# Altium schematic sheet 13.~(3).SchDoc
size 398 x 287 mm
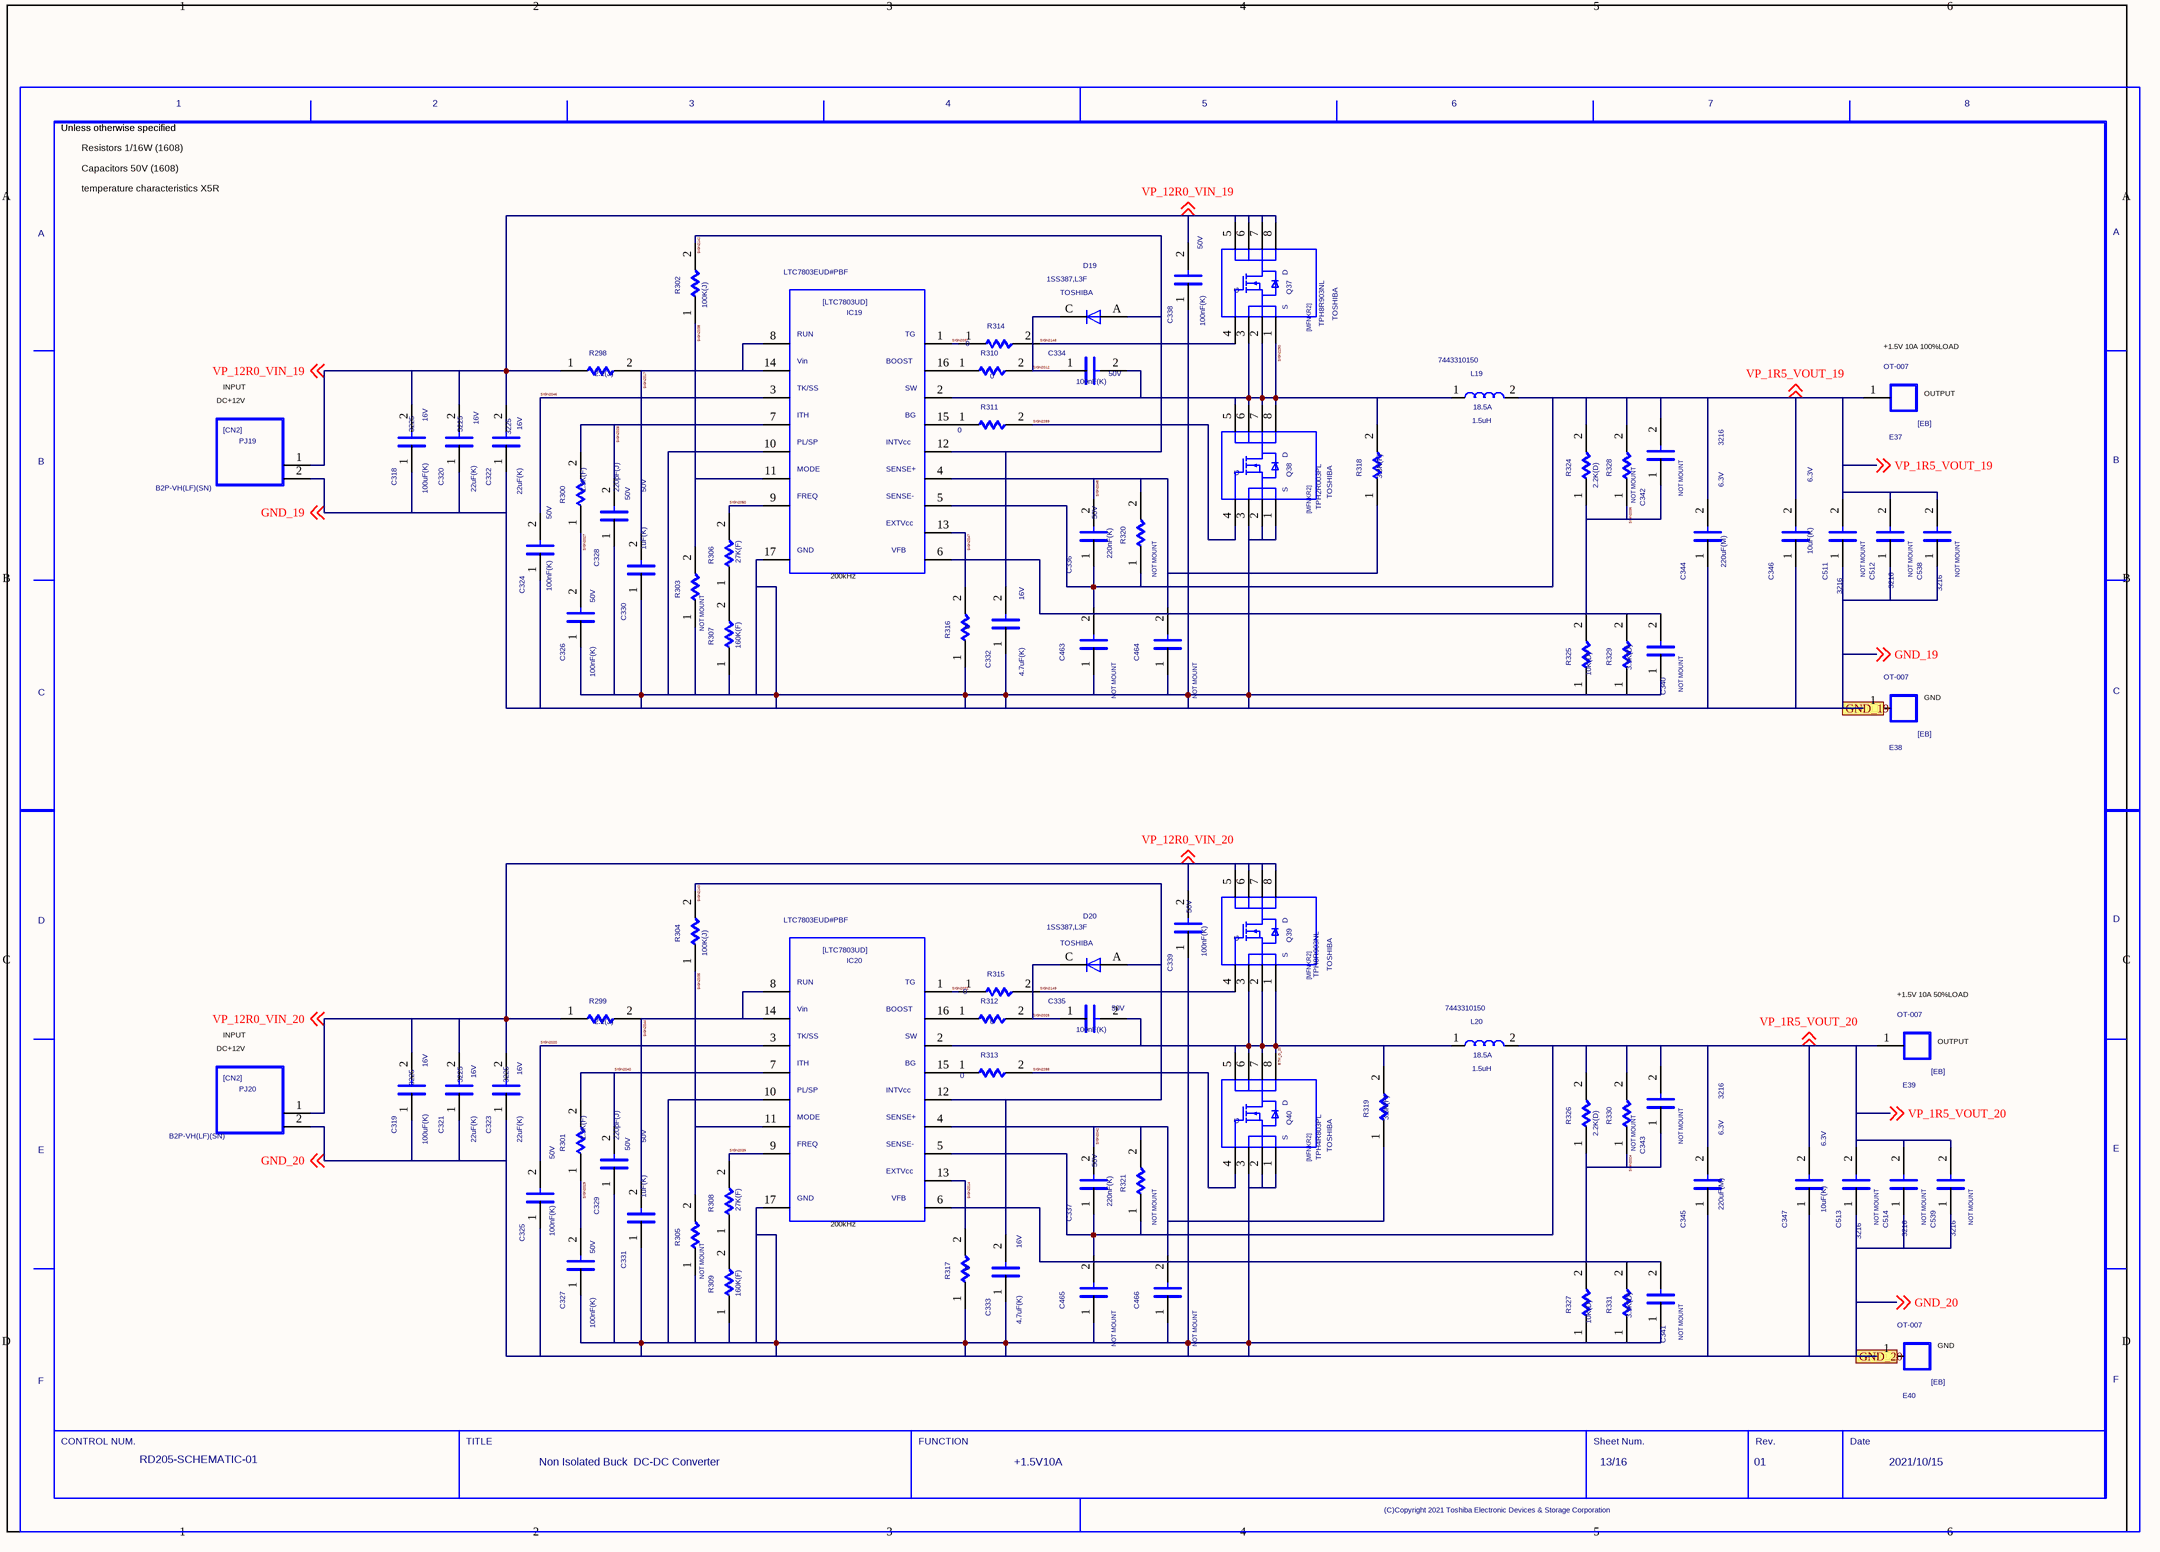
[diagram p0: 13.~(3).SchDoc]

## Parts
C318  SIZECODESMD: 3225  VAL2: 16V  VAL1: 100uF(K)  (hidden comment: C)
C319  SIZECODESMD: 3225  VAL2: 16V  VAL1: 100uF(K)  (hidden comment: C)
C320  SIZECODESMD: 3225  VAL2: 16V  VAL1: 22uF(K)  (hidden comment: C)
C321  SIZECODESMD: 3225  VAL2: 16V  VAL1: 22uF(K)  (hidden comment: C)
C322  SIZECODESMD: 3225  VAL2: 16V  VAL1: 22uF(K)  (hidden comment: C)
C323  SIZECODESMD: 3225  VAL2: 16V  VAL1: 22uF(K)  (hidden comment: C)
C324  VAL2: 50V  VAL1: 100nF(K)  (hidden comment: C)
C325  VAL2: 50V  VAL1: 100nF(K)  (hidden comment: C)
C326  VAL2: 50V  VAL1: 100nF(K)  (hidden comment: C)
C327  VAL2: 50V  VAL1: 100nF(K)  (hidden comment: C)
C328  VAL2: 50V  VAL1: 220pF(J)  (hidden comment: C)
C329  VAL2: 50V  VAL1: 220pF(J)  (hidden comment: C)
C330  VAL2: 50V  VAL1: 1uF(K)  (hidden comment: C)
C331  VAL2: 50V  VAL1: 1uF(K)  (hidden comment: C)
C332  VAL2: 16V  VAL1: 4.7uF(K)  (hidden comment: C)
C333  VAL2: 16V  VAL1: 4.7uF(K)  (hidden comment: C)
C334  VAL2: 50V  VAL1: 100nF(K)  (hidden comment: C)
C335  VAL2: 50V  VAL1: 100nF(K)  (hidden comment: C)
C336  VAL2: 50V  VAL1: 220nF(K)  (hidden comment: C)
C337  VAL2: 50V  VAL1: 220nF(K)  (hidden comment: C)
C338  VAL2: 50V  VAL1: 100nF(K)  (hidden comment: C)
C339  VAL2: 50V  VAL1: 100nF(K)  (hidden comment: C)
C340  NOTMOUNT: NOT MOUNT  (hidden comment: C)
C341  NOTMOUNT: NOT MOUNT  (hidden comment: C)
C342  NOTMOUNT: NOT MOUNT  (hidden comment: C)
C343  NOTMOUNT: NOT MOUNT  (hidden comment: C)
C344  SIZECODESMD: 3216  VAL2: 6.3V  VAL1: 220uF(M)  (hidden comment: C)
C345  SIZECODESMD: 3216  VAL2: 6.3V  VAL1: 220uF(M)  (hidden comment: C)
C346  VAL2: 6.3V  VAL1: 10uF(K)  (hidden comment: C)
C347  VAL2: 6.3V  VAL1: 10uF(K)  (hidden comment: C)
C463  NOTMOUNT: NOT MOUNT  (hidden comment: C)
C464  NOTMOUNT: NOT MOUNT  (hidden comment: C)
C465  NOTMOUNT: NOT MOUNT  (hidden comment: C)
C466  NOTMOUNT: NOT MOUNT  (hidden comment: C)
C511  NOTMOUNT: NOT MOUNT  SIZECODESMD: 3216  (hidden comment: C)
C512  NOTMOUNT: NOT MOUNT  SIZECODESMD: 3216  (hidden comment: C)
C513  NOTMOUNT: NOT MOUNT  SIZECODESMD: 3216  (hidden comment: C)
C514  NOTMOUNT: NOT MOUNT  SIZECODESMD: 3216  (hidden comment: C)
C538  NOTMOUNT: NOT MOUNT  SIZECODESMD: 3216  (hidden comment: C)
C539  NOTMOUNT: NOT MOUNT  SIZECODESMD: 3216  (hidden comment: C)
D19  USERCOMPTEXT3: TOSHIBA  VAL3: 1SS387,L3F  (hidden comment: D)
D20  USERCOMPTEXT3: TOSHIBA  VAL3: 1SS387,L3F  (hidden comment: D)
E37  VAL3: OT-007  (hidden comment: EB)
E38  VAL3: OT-007  (hidden comment: EB)
E39  VAL3: OT-007  (hidden comment: EB)
E40  VAL3: OT-007  (hidden comment: EB)
IC19  VAL3: LTC7803EUD#PBF  (hidden comment: LTC7803UD)
IC20  VAL3: LTC7803EUD#PBF  (hidden comment: LTC7803UD)
L19  VAL3: 7443310150  VAL2: 18.5A  VAL1: 1.5uH  (hidden comment: L)
L20  VAL3: 7443310150  VAL2: 18.5A  VAL1: 1.5uH  (hidden comment: L)
PJ19  VAL3: B2P-VH(LF)(SN)  (hidden comment: CN2)
PJ20  VAL3: B2P-VH(LF)(SN)  (hidden comment: CN2)
Q37  USERCOMPTEXT3: TOSHIBA  VAL3: TPH8R903NL  (hidden comment: MFNKR2)
Q38  USERCOMPTEXT3: TOSHIBA  VAL3: TPH2R003PL  (hidden comment: MFNKR2)
Q39  USERCOMPTEXT3: TOSHIBA  VAL3: TPH8R903NL  (hidden comment: MFNKR2)
Q40  USERCOMPTEXT3: TOSHIBA  VAL3: TPH4R803PL  (hidden comment: MFNKR2)
R298  VAL1: 2.2(J)  (hidden comment: R)
R299  VAL1: 2.2(J)  (hidden comment: R)
R300  VAL1: 1.3K(F)  (hidden comment: R)
R301  VAL1: 1.3K(F)  (hidden comment: R)
R302  VAL1: 100K(J)  (hidden comment: R)
R303  NOTMOUNT: NOT MOUNT  (hidden comment: R)
R304  VAL1: 100K(J)  (hidden comment: R)
R305  NOTMOUNT: NOT MOUNT  (hidden comment: R)
R306  VAL1: 27K(F)  (hidden comment: R)
R307  VAL1: 160K(F)  (hidden comment: R)
R308  VAL1: 27K(F)  (hidden comment: R)
R309  VAL1: 160K(F)  (hidden comment: R)
R310  VAL1: 0  (hidden comment: R)
R311  VAL1: 0  (hidden comment: R)
R312  VAL1: 0  (hidden comment: R)
R313  VAL1: 0  (hidden comment: R)
R314  VAL1: 0  (hidden comment: R)
R315  VAL1: 0  (hidden comment: R)
R316  VAL1: 0  (hidden comment: R)
R317  VAL1: 0  (hidden comment: R)
R318  VAL1: 3.3K(F)  (hidden comment: R)
R319  VAL1: 3.3K(F)  (hidden comment: R)
R320  NOTMOUNT: NOT MOUNT  (hidden comment: R)
R321  NOTMOUNT: NOT MOUNT  (hidden comment: R)
R324  VAL1: 2.2K(D)  (hidden comment: R)
R325  VAL1: 10K(D)  (hidden comment: R)
R326  VAL1: 2.2K(D)  (hidden comment: R)
R327  VAL1: 10K(D)  (hidden comment: R)
R328  NOTMOUNT: NOT MOUNT  (hidden comment: R)
R329  VAL1: 3.3K(D)  (hidden comment: R)
R330  NOTMOUNT: NOT MOUNT  (hidden comment: R)
R331  VAL1: 3.3K(D)  (hidden comment: R)
U?  DATE: 2021/10/15  SHEETNUMBER: 13/16  TITLE: Non Isolated Buck / DC-DC Converter  REVISION: 01  DRAWINGNUMBER: RD205-SCHEMATIC-01  FUNCTION: +1.5V10A  (hidden comment: WAKU_DEF100)

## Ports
GND_19, GND_20

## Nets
BTM_D_20: C335.2 IC20.2 L20.1 Q39.1 Q39.2 Q39.3 Q40.5 Q40.6 Q40.7 Q40.8 R319.2
GND_19: C318.1 C320.1 C322.1 C324.1 C326.1 C328.1 C330.1 C332.1 C338.1 C340.1 C344.1 C346.1 C463.1 C464.1 C511.1 C512.1 C538.1 E38.1 IC19.10 IC19.17 PJ19.2 Q38.1 Q38.2 Q38.3 R303.1 R307.1 R316.1 R325.1 R329.1 ; off-sheet GND_19, port GND_19
GND_20: C319.1 C321.1 C323.1 C325.1 C327.1 C329.1 C331.1 C333.1 C339.1 C341.1 C345.1 C347.1 C465.1 C466.1 C513.1 C514.1 C539.1 E40.1 IC20.10 IC20.17 PJ20.2 Q40.1 Q40.2 Q40.3 R305.1 R309.1 R317.1 R327.1 R331.1 ; off-sheet GND_20, port GND_20
SIGN2012: C334.1 D19.C R310.2
SIGN2014: IC20.13 R317.2
SIGN2017: C330.2 IC19.8 IC19.14 R298.2
SIGN2020: C325.2 IC20.3
SIGN2024: C341.2 C343.1 IC20.6 R326.1 R327.2 R330.1 R331.2
SIGN2026: C335.1 D20.C R312.2
SIGN2027: C326.2 R300.1
SIGN2028: C328.2 IC19.7 R300.2
SIGN2029: C327.2 R301.1
SIGN2031: IC20.1 R315.1
SIGN2035: IC20.11 R304.1 R305.2
SIGN2036: C340.2 C342.1 IC19.6 R324.1 R325.2 R328.1 R329.2
SIGN2037: IC19.1 R314.1
SIGN2038: IC19.11 R302.1 R303.2
SIGN2039: IC20.9 R308.2
SIGN2040: C329.2 IC20.7 R301.2
SIGN2042: C337.2 C466.2 IC20.4 R319.1 R321.2
SIGN2044: C331.2 IC20.8 IC20.14 R299.2
SIGN2045: C336.2 C464.2 IC19.4 R318.1 R320.2
SIGN2046: C324.2 IC19.3
SIGN2047: IC19.13 R316.2
SIGN2050: IC19.9 R306.2
SIGN2142: C332.2 D19.A IC19.12 R302.2
SIGN2143: C333.2 D20.A IC20.12 R304.2
SIGN2148: Q37.4 R314.2
SIGN2149: Q39.4 R315.2
SIGN2288: Q40.4 R313.2
SIGN2289: Q38.4 R311.2
SIGN2290: C334.2 IC19.2 L19.1 Q37.1 Q37.2 Q37.3 Q38.5 Q38.6 Q38.7 Q38.8 R318.2
VP_1R5_VOUT_19: C336.1 C342.2 C344.2 C346.2 C463.2 C511.2 C512.2 C538.2 E37.1 IC19.5 L19.2 R320.1 R324.2 R328.2 ; off-sheet VP_1R5_VOUT_19
VP_1R5_VOUT_20: C337.1 C343.2 C345.2 C347.2 C465.2 C513.2 C514.2 C539.2 E39.1 IC20.5 L20.2 R321.1 R326.2 R330.2 ; off-sheet VP_1R5_VOUT_20
VP_12R0_VIN_19: C318.2 C320.2 C322.2 C338.2 PJ19.1 Q37.5 Q37.6 Q37.7 Q37.8 R298.1 ; off-sheet VP_12R0_VIN_19
VP_12R0_VIN_20: C319.2 C321.2 C323.2 C339.2 PJ20.1 Q39.5 Q39.6 Q39.7 Q39.8 R299.1 ; off-sheet VP_12R0_VIN_20
NetIC19_15: IC19.15 R311.1
NetIC19_16: IC19.16 R310.1
NetIC20_15: IC20.15 R313.1
NetIC20_16: IC20.16 R312.1
NetR306_1: R306.1 R307.2
NetR308_1: R308.1 R309.2

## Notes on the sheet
- Unless otherwise specified
- Resistors 1/16W (1608)
- Capacitors 50V (1608)
- temperature characteristics X5R
- DC+12V
- INPUT
- (near E37) +1.5V 10A 100%LOAD
- (near E37) OUTPUT
- (near IC19) 200kHz
- (near E38) GND
- (near E39) +1.5V 10A 50%LOAD
- (near E39) OUTPUT
- (near IC20) 200kHz
- (near E40) GND

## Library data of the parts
C318 C319 = C: SQ_PART_MODEL: CON_100n; FNPARTSNAMEG: CHIP CERAMIC CAPACITOR (3225); USEINPARTSLIST: YES; OriginalSymbolOrigin: (2540,7620); MFSOLDERINGPROP: .; TEMPCHARACTERI2: B; MFFORMINGDIVP: KC; OUMECLASSIFICATION: セラミックコンデンサ; MFMOUNTSYMBOLP: 90; CDMASTERCADCELG: DC903A; PCODE: P03276001115; FNCLASSCODEG: P03-03; MAXGCOUNT: 1; RATEDVOLTAGE: 250; COMPONENTNAME: G36030160049; OUMEMAKER: KYC 京セラ; MFPACKAGEMETHOP: S; NOMINALCAPACITA: 100n; OUMEMAKERKATAMEI: CF32W5R104K250AT; CAPACITANCETOLE: K
C320-C323 = C: SQ_PART_MODEL: CON_22u; FNPARTSNAMEG: CHIP CERAMIC CAPACITOR (3225); USEINPARTSLIST: YES; OriginalSymbolOrigin: (2540,7620); MFSOLDERINGPROP: .; TEMPCHARACTERI2: B; MFFORMINGDIVP: KC; OUMECLASSIFICATION: セラミックコンデンサ; MFMOUNTSYMBOLP: 80; CDMASTERCADCELG: DC903A; PCODE: P03043035626; FNCLASSCODEG: P03-03; MAXGCOUNT: 1; RATEDVOLTAGE: 6.3; COMPONENTNAME: G36030119054; OUMEMAKER: TYD 太陽誘電; MFPACKAGEMETHOP: S; NOMINALCAPACITA: 22u; OUMEMAKERKATAMEI: JMK325BJ226KM-T; CAPACITANCETOLE: K
C324-C327 C334 C335 C338 C339 = C: SQ_PART_MODEL: CON_100n; FNPARTSNAMEG: CHIP CERAMIC CAPACITOR (1608); USEINPARTSLIST: YES; OriginalSymbolOrigin: (2540,7620); MFSOLDERINGPROP: .; TEMPCHARACTERI2: B; MFFORMINGDIVP: KC; OUMECLASSIFICATION: セラミックコンデンサ; SIZECODESMD: 1608; MFMOUNTSYMBOLP: 80; CDMASTERCADCELG: C8100E; PCODE: P03B000000E4; FNCLASSCODEG: P03-03; MAXGCOUNT: 1; RATEDVOLTAGE: 16; COMPONENTNAME: GDM030000598; OUMEMAKER: MRT 村田製作所; MFPACKAGEMETHOP: S; NOMINALCAPACITA: 100n; OUMEMAKERKATAMEI: GRM188B11C104KA01C; CAPACITANCETOLE: K
C328 C329 = C: SQ_PART_MODEL: CON_220p; FNPARTSNAMEG: CHIP CERAMIC CAPACITOR (1608); USEINPARTSLIST: YES; OriginalSymbolOrigin: (2540,7620); CDMASTERCADCELG: C8100E; MFSOLDERINGPROP: .; TEMPCHARACTERI2: CH; MFFORMINGDIVP: KC; OUMECLASSIFICATION: セラミックコンデンサ; SIZECODESMD: 1608; MFMOUNTSYMBOLP: 80; PCODE: P03039269127; FNCLASSCODEG: P03-03; MAXGCOUNT: 1; RATEDVOLTAGE: 50; COMPONENTNAME: GDM030000578; OUMEMAKER: KYC 京セラ; MFPACKAGEMETHOP: S; NOMINALCAPACITA: 220p; OUMEMAKERKATAMEI: CM105CH221J50AT; CAPACITANCETOLE: J
C330 C331 = C: SQ_PART_MODEL: CON_1u; FNPARTSNAMEG: CHIP CERAMIC CAPACITOR (1608); USEINPARTSLIST: YES; OriginalSymbolOrigin: (2540,7620); MFSOLDERINGPROP: .; TEMPCHARACTERI2: B; MFFORMINGDIVP: KC; OUMECLASSIFICATION: セラミックコンデンサ; SIZECODESMD: 1608; MFMOUNTSYMBOLP: 80; CDMASTERCADCELG: C8100E; PCODE: P03039ACE122; FNCLASSCODEG: P03-03; MAXGCOUNT: 1; RATEDVOLTAGE: 6.3; COMPONENTNAME: G36030104159; OUMEMAKER: KYC 京セラ; MFPACKAGEMETHOP: S; NOMINALCAPACITA: 1u; OUMEMAKERKATAMEI: CM105B105K06ATN; CAPACITANCETOLE: K
C332 C333 = C: SQ_PART_MODEL: CON_4.7u; FNPARTSNAMEG: CHIP CERAMIC CAPACITOR (1608); USEINPARTSLIST: YES; OriginalSymbolOrigin: (2540,7620); MFSOLDERINGPROP: .; TEMPCHARACTERI2: B; MFFORMINGDIVP: KC; OUMECLASSIFICATION: セラミックコンデンサ; SIZECODESMD: 1608; MFMOUNTSYMBOLP: 80; CDMASTERCADCELG: C8100E; PCODE: P03B000000MS; FNCLASSCODEG: P03-03; MAXGCOUNT: 1; RATEDVOLTAGE: 4; COMPONENTNAME: GDM030000053; OUMEMAKER: KYC 京セラ; MFPACKAGEMETHOP: S; NOMINALCAPACITA: 4.7u; OUMEMAKERKATAMEI: CM105B475M04AT; CAPACITANCETOLE: M
C336 C337 = C: SQ_PART_MODEL: CON_220n; FNPARTSNAMEG: CHIP CERAMIC CAPACITOR (1608); PARTCOMMENT: 代表セル<KC0008> がフットプリントに登録されていません。; USEINPARTSLIST: YES; OriginalSymbolOrigin: (2540,7620); MFSOLDERINGPROP: .; TEMPCHARACTERI2: B; MFFORMINGDIVP: KC; OUMECLASSIFICATION: セラミックコンデンサ; SIZECODESMD: 1608; MFMOUNTSYMBOLP: 80; CDMASTERCADCELG: KC0008; PCODE: P03B000001L3; FNCLASSCODEG: P03-03; MAXGCOUNT: 1; RATEDVOLTAGE: 16; COMPONENTNAME: GDM030001129; OUMEMAKER: MRT 村田製作所; MFPACKAGEMETHOP: S; NOMINALCAPACITA: 220n; OUMEMAKERKATAMEI: GRM188B11C224KA01D; CAPACITANCETOLE: K
C340-C343 = C: SQ_PART_MODEL: CON_100p; FNPARTSNAMEG: CHIP CERAMIC CAPACITOR (1608); USEINPARTSLIST: YES; OriginalSymbolOrigin: (2540,7620); TOLERANCE: J; ASIMVALUE: 100P; MFSOLDERINGPROP: .; TEMPCHARACTERI2: CH; MFFORMINGDIVP: KC; OUMECLASSIFICATION: セラミックコンデンサ; SIZECODESMD: 1608; MFMOUNTSYMBOLP: 80; CDMASTERCADCELG: C8100E; PCODE: P03039177125; FNCLASSCODEG: P03-03; MAXGCOUNT: 1; RATEDVOLTAGE: 50; COMPONENTNAME: G36030011365; OUMEMAKER: KYC 京セラ; MFPACKAGEMETHOP: S; OUMEMAKERKATAMEI: CM105CH101J50AT; VAL2: 50V; VAL1: 100pF(J)
C344 C345 = C: SQ_PART_MODEL: CON_22u; FNPARTSNAMEG: CHIP CERAMIC CAPACITOR (3216); USEINPARTSLIST: YES; OriginalSymbolOrigin: (2540,7620); MFSOLDERINGPROP: .; TEMPCHARACTERI2: B; MFFORMINGDIVP: KC; OUMECLASSIFICATION: セラミックコンデンサ; MFMOUNTSYMBOLP: 80; CDMASTERCADCELG: DC901A; PCODE: P03B0000004V; FNCLASSCODEG: P03-03; MAXGCOUNT: 1; RATEDVOLTAGE: 6.3; COMPONENTNAME: GDM030000020; OUMEMAKER: KYC 京セラ; MFPACKAGEMETHOP: S; NOMINALCAPACITA: 22u; OUMEMAKERKATAMEI: CM316B226M06AT; CAPACITANCETOLE: M
C346 C347 = C: SQ_PART_MODEL: CON_1u; FNPARTSNAMEG: CHIP CERAMIC CAPACITOR (1608); PARTCOMMENT: 代表セル<KC0008> がフットプリントに登録されていません。; USEINPARTSLIST: YES; OriginalSymbolOrigin: (2540,7620); MFSOLDERINGPROP: .; TEMPCHARACTERI2: B; MFFORMINGDIVP: KC; OUMECLASSIFICATION: セラミックコンデンサ; SIZECODESMD: 1608; MFMOUNTSYMBOLP: 80; CDMASTERCADCELG: KC0008; PCODE: P03B000000ZQ; FNCLASSCODEG: P03-03; MAXGCOUNT: 1; RATEDVOLTAGE: 6.3; COMPONENTNAME: GDM030000202; OUMEMAKER: MRT 村田製作所; MFPACKAGEMETHOP: S; NOMINALCAPACITA: 1u; OUMEMAKERKATAMEI: GRM185B10J105KE21D; CAPACITANCETOLE: K
C463-C466 = C: SQ_PART_MODEL: CON_220n; FNPARTSNAMEG: CHIP CERAMIC CAPACITOR (1608); PARTCOMMENT: 代表セル<KC0008> がフットプリントに登録されていません。; USEINPARTSLIST: YES; OriginalSymbolOrigin: (2540,7620); MFSOLDERINGPROP: .; TEMPCHARACTERI2: B; MFFORMINGDIVP: KC; OUMECLASSIFICATION: セラミックコンデンサ; SIZECODESMD: 1608; MFMOUNTSYMBOLP: 80; CDMASTERCADCELG: KC0008; PCODE: P03B000001L3; FNCLASSCODEG: P03-03; MAXGCOUNT: 1; RATEDVOLTAGE: 16; COMPONENTNAME: GDM030001129; OUMEMAKER: MRT 村田製作所; MFPACKAGEMETHOP: S; NOMINALCAPACITA: 220n; OUMEMAKERKATAMEI: GRM188B11C224KA01D; VAL2: 16V; VAL1: 220nF(K); CAPACITANCETOLE: K
C511-C514 C538 C539 = C: SQ_PART_MODEL: CON_22u; FNPARTSNAMEG: CHIP CERAMIC CAPACITOR (3216); USEINPARTSLIST: YES; OriginalSymbolOrigin: (2540,7620); MFSOLDERINGPROP: .; TEMPCHARACTERI2: B; MFFORMINGDIVP: KC; OUMECLASSIFICATION: セラミックコンデンサ; MFMOUNTSYMBOLP: 80; CDMASTERCADCELG: DC901A; PCODE: P03B0000004V; FNCLASSCODEG: P03-03; MAXGCOUNT: 1; RATEDVOLTAGE: 6.3; COMPONENTNAME: GDM030000020; OUMEMAKER: KYC 京セラ; MFPACKAGEMETHOP: S; NOMINALCAPACITA: 22u; OUMEMAKERKATAMEI: CM316B226M06AT; VAL2: 6.3V; VAL1: 22uF(M); CAPACITANCETOLE: M
D19 D20 = D: FNPARTSNAMEG: DIODE; USEINPARTSLIST: YES; PARTNAME: GDM420000143; SAVEAREA0: -565,-171,12979,8058; SAVECOUNT: 1; TIME: 14:49:55; UPDATEUSER: 19870035; UPDATETIME: 14:20:16; OriginalSymbolOrigin: (5080,5080); FORWARDVOLTAGEM: 0; MAXREVERSEVOLTA: 80; COMPONENTNAME: GDM420000143_package; MFSOLDERINGPROP: .; OUMEMAKER: TSB 東芝（ＹＰＳＳ）; QUADMODEL: dummymodel; MFPACKAGEMETHOP: S; MFFORMINGDIVP: MM; MOUNTINGFORMSMD: SMD; OUMECLASSIFICATION: 小信号ダイオード; OUMEMAKERKATAMEI: 1SS387(TPH3,F); CDMASTERCADCELG: D8101D; PCODE: P42B0000008E; FNCLASSCODEG: P42-01
E37-E40 = EB: FNPARTSNAMEG: TERMINAL; USEINPARTSLIST: YES; PARTNAME: 5P9L1232P001; OUMEPARTTYPE: TB; OriginalSymbolOrigin: (2540,12700); COMPONENTNAME: 5P9L1232P001_package; MAXGCOUNT: 1; MFSOLDERINGPROP: .; OUMEMAKER: オサダ; QUADMODEL: dummymodel; MFPACKAGEMETHOP: I; MFFORMINGDIVP: OD; OUMECLASSIFICATION: 端子台、端子板; CDMASTERCADCELG: DE0009; KIND: PBS; PCODE: P29045001117; TERMINALSTYLE: SC; FNCLASSCODEG: P29-01
IC19 IC20 = LTC7803UD: USEINPARTSLIST: YES; SAVECOUNT: 29; SAVEAREA0: -53177,0,89020,58420; TIME: 16:14:14; UPDATEUSER: q91866sr; UPDATETIME: 13:15:36; OriginalSymbolOrigin: (5080,55880); MAXGCOUNT: 1; COMPONENTNAME: LTC7803UD_LTC7803UD; OUMEMAKER: ANALOG DEVICES
L19 L20 = L: USEINPARTSLIST: YES; PARTNAME: 7443310047; OriginalSymbolOrigin: (2540,5080); COMPONENTNAME: L_L; MAXGCOUNT: 1; OUMEMAKER: WURTH
PJ19 PJ20 = CN2: FNPARTSNAMEG: 3.96PITCH NYLON CONNECTOR; USEINPARTSLIST: YES; PARTNAME: G36220114012; OUMEPARTTYPE: CN; OriginalSymbolOrigin: (2540,15240); MAXGCOUNT: 1; RATEDCURRENT: 7; COMPONENTNAME: G36220114012_package; MFSOLDERINGPROP: .; OUMEMAKER: JST 日本圧着端子製造; NUMBEROFCONTACT: 2; QUADMODEL: dummymodel; MFPACKAGEMETHOP: I; MFFORMINGDIVP: CU; CONTACTPITCH: 3.96m; OUMEMAKERKATAMEI: B2P-VH; CDMASTERCADCELG: DPJ514; PCODE: P22346001114; TERMINALSTYLE: PW; FNCLASSCODEG: P22-10
Q37-Q40 = MFNKR2: USEINPARTSLIST: YES; PARTNAME: TPH6R003NL; SAVEAREA0: -9199,-39,32138,22820; TIME: 18:57:44; UPDATEUSER: q91866sr; UPDATETIME: 12:36:02; SAVECOUNT: 10; OriginalSymbolOrigin: (5080,20320); MAXGCOUNT: 1; COMPONENTNAME: MFNKR2_MFNKR2
R298 R299 = R: SQ_PART_MODEL: RES_2.2; FNPARTSNAMEG: CHIP RESISTOR (1608); USEINPARTSLIST: YES; OriginalSymbolOrigin: (5080,5080); TOLERANCE: J; ASIMVALUE: 2.2; MAXGCOUNT: 1; COMPONENTNAME: G36010011507; MFSOLDERINGPROP: .; OUMEMAKER: NAE 松下電子部品; MFPACKAGEMETHOP: S; MFFORMINGDIVP: KC; MOUNTINGFORMSMD: SMD; OUMECLASSIFICATION: 表面実装用固定抵抗器; MFMOUNTSYMBOLP: 80; POWERRATING: 63m; OUMEMAKERKATAMEI: ERJ3GEYJ2R2V; NUMBEROFELEMENT: 0; VAL2: 62.5mW; CDMASTERCADCELG: DR802R; PCODE: P01042157622; FNCLASSCODEG: P01-08
R300 R301 = R: SQ_PART_MODEL: RES_1.3K; FNPARTSNAMEG: CHIP RESISTOR (1608); USEINPARTSLIST: YES; OriginalSymbolOrigin: (5080,5080); TOLERANCE: F; ASIMVALUE: 1.3K; MAXGCOUNT: 1; COMPONENTNAME: G36010104049; MFSOLDERINGPROP: .; OUMEMAKER: HDK 北陸電気工業; MFPACKAGEMETHOP: S; MFFORMINGDIVP: KC; MOUNTINGFORMSMD: SMD; OUMECLASSIFICATION: 表面実装用固定抵抗器; MFMOUNTSYMBOLP: 80; POWERRATING: 63m; OUMEMAKERKATAMEI: CR1/16 132FV; NUMBEROFELEMENT: 0; VAL2: 62.5mW; CDMASTERCADCELG: DR802R; PCODE: P01042017223; FNCLASSCODEG: P01-08
R302 R304 = R: SQ_PART_MODEL: RES_100K; FNPARTSNAMEG: CHIP RESISTOR (1608); USEINPARTSLIST: YES; OriginalSymbolOrigin: (5080,5080); TOLERANCE: J; ASIMVALUE: 100K; MFSOLDERINGPROP: .; MFPACKAGEMETHOP: S; MFFORMINGDIVP: KC; MOUNTINGFORMSMD: SMD; MFMOUNTSYMBOLP: 80; NUMBEROFELEMENT: 0; PCODE: P01042047220; MAXGCOUNT: 1; COMPONENTNAME: G36010011057; OUMEMAKER: HDK 北陸電気工業; OUMECLASSIFICATION: 表面実装用固定抵抗器; POWERRATING: 63m; OUMEMAKERKATAMEI: CR1/16 104JV; VAL2: 62.5mW; CDMASTERCADCELG: DR802R; FNCLASSCODEG: P01-08
R303 R305 = R: SQ_PART_MODEL: RES_10; FNPARTSNAMEG: CHIP RESISTOR (1608); USEINPARTSLIST: YES; OriginalSymbolOrigin: (5080,5080); TOLERANCE: F; ASIMVALUE: 10; MFSOLDERINGPROP: .; MFPACKAGEMETHOP: S; MFFORMINGDIVP: KC; MOUNTINGFORMSMD: SMD; MFMOUNTSYMBOLP: 80; NUMBEROFELEMENT: 0; PCODE: P01042036620; MAXGCOUNT: 1; COMPONENTNAME: G36010104063; OUMEMAKER: NAE 松下電子部品; OUMECLASSIFICATION: 表面実装用固定抵抗器; POWERRATING: 63m; OUMEMAKERKATAMEI: ERJ3GEYF100V; VAL2: 62.5mW; VAL1: 10(F); CDMASTERCADCELG: DR802R; FNCLASSCODEG: P01-08
R306 R308 = R: SQ_PART_MODEL: RES_27K; FNPARTSNAMEG: CHIP RESISTOR (1608); USEINPARTSLIST: YES; OriginalSymbolOrigin: (5080,5080); MAXGCOUNT: 1; TOLERANCE: F; COMPONENTNAME: G36010027195; MFSOLDERINGPROP: .; OUMEMAKER: NAE 松下電子部品; MFPACKAGEMETHOP: S; MFFORMINGDIVP: KC; MOUNTINGFORMSMD: SMD; OUMECLASSIFICATION: 表面実装用固定抵抗器; ASIMVALUE: 27K; MFMOUNTSYMBOLP: 80; POWERRATING: 63m; OUMEMAKERKATAMEI: ERJ3GEYF273V; NUMBEROFELEMENT: 0; VAL2: 62.5mW; CDMASTERCADCELG: DR802R; PCODE: P01042508622; FNCLASSCODEG: P01-08
R307 R309 = R: SQ_PART_MODEL: RES_160K; FNPARTSNAMEG: CHIP RESISTOR (1608); USEINPARTSLIST: YES; OriginalSymbolOrigin: (5080,5080); MAXGCOUNT: 1; COMPONENTNAME: G51011061108; MFSOLDERINGPROP: .; OUMEMAKER: HDK 北陸電気工業; MFPACKAGEMETHOP: S; MFFORMINGDIVP: KC; MOUNTINGFORMSMD: SMD; OUMECLASSIFICATION: 表面実装用固定抵抗器; RESISTANCETOLER: F; MFMOUNTSYMBOLP: 80; POWERRATING: 63m; OUMEMAKERKATAMEI: CR1/16 164FV; NOMINALRESISTAN: 160K; NUMBEROFELEMENT: 0; VAL2: 62.5mW; CDMASTERCADCELG: DR802R; PCODE: P01042125225; FNCLASSCODEG: P01-08
R310 R312 R316 R317 = R: SQ_PART_MODEL: RES_10; FNPARTSNAMEG: CHIP RESISTOR (1608); USEINPARTSLIST: YES; OriginalSymbolOrigin: (5080,5080); TOLERANCE: F; ASIMVALUE: 10; MFSOLDERINGPROP: .; MFPACKAGEMETHOP: S; MFFORMINGDIVP: KC; MOUNTINGFORMSMD: SMD; MFMOUNTSYMBOLP: 80; PCODE: P01042036620; MAXGCOUNT: 1; COMPONENTNAME: G36010104063; OUMEMAKER: NAE 松下電子部品; OUMECLASSIFICATION: 表面実装用固定抵抗器; POWERRATING: 63m; OUMEMAKERKATAMEI: ERJ3GEYF100V; VAL2: 62.5mW; CDMASTERCADCELG: DR802R; FNCLASSCODEG: P01-08
R311 R313-R315 = R: SQ_PART_MODEL: RES_10; FNPARTSNAMEG: CHIP RESISTOR (2012); USEINPARTSLIST: YES; OriginalSymbolOrigin: (5080,5080); MAXGCOUNT: 1; TOLERANCE: F; COMPONENTNAME: 5P9L1083P100; MFSOLDERINGPROP: .; OUMEMAKER: 北陸電気工業; MFPACKAGEMETHOP: S; MFFORMINGDIVP: KC; MOUNTINGFORMSMD: SMD; OUMECLASSIFICATION: 表面実装用固定抵抗器; ASIMVALUE: 10; MFMOUNTSYMBOLP: 90; POWERRATING: 100m; OUMEMAKERKATAMEI: CR1/10 100FV Pb(F); VAL2: 125mW; CDMASTERCADCELG: DR910A; PCODE: P01043091222; FNCLASSCODEG: P01-08
R318 R319 = R: SQ_PART_MODEL: RES_3.3K; FNPARTSNAMEG: CHIP RESISTOR (1608); USEINPARTSLIST: YES; OriginalSymbolOrigin: (5080,5080); TOLERANCE: F; ASIMVALUE: 3.3K; MAXGCOUNT: 1; COMPONENTNAME: G36010027027; MFSOLDERINGPROP: .; OUMEMAKER: ROH ロー・; MFPACKAGEMETHOP: S; MFFORMINGDIVP: KC; MOUNTINGFORMSMD: SMD; OUMECLASSIFICATION: 表面実装用固定抵抗器; MFMOUNTSYMBOLP: 80; POWERRATING: 63m; OUMEMAKERKATAMEI: MCR03EZPFX3301; NUMBEROFELEMENT: 0; VAL2: 62.5mW; CDMASTERCADCELG: DR802R; PCODE: P01042250729; FNCLASSCODEG: P01-08
R320 R321 = R: SQ_PART_MODEL: RES_68K; FNPARTSNAMEG: CHIP RESISTOR (1608); USEINPARTSLIST: YES; OriginalSymbolOrigin: (5080,5080); TOLERANCE: F; ASIMVALUE: 68K; MAXGCOUNT: 1; COMPONENTNAME: G36010027126; MFSOLDERINGPROP: .; OUMEMAKER: HDK 北陸電気工業; MFPACKAGEMETHOP: S; MFFORMINGDIVP: KC; MOUNTINGFORMSMD: SMD; OUMECLASSIFICATION: 表面実装用固定抵抗器; MFMOUNTSYMBOLP: 80; POWERRATING: 63m; OUMEMAKERKATAMEI: CR1/16 683FV; NUMBEROFELEMENT: 0; VAL2: 62.5mW; VAL1: 68K(F); CDMASTERCADCELG: DR802R; PCODE: P01042456220; FNCLASSCODEG: P01-08
R324 R326 = R: SQ_PART_MODEL: RES_2.2K; FNPARTSNAMEG: CHIP RESISTOR (1608); USEINPARTSLIST: YES; OriginalSymbolOrigin: (5080,5080); MAXGCOUNT: 1; COMPONENTNAME: G36010129332; MFSOLDERINGPROP: .; OUMEMAKER: NAE 松下電子部品; MFPACKAGEMETHOP: S; MFFORMINGDIVP: KC; MOUNTINGFORMSMD: SMD; OUMECLASSIFICATION: 表面実装用固定抵抗器; RESISTANCETOLER: D; MFMOUNTSYMBOLP: 80; POWERRATING: 63m; OUMEMAKERKATAMEI: ERJ3RBD222V; NOMINALRESISTAN: 2.2K; NUMBEROFELEMENT: 0; VAL2: 62.5mW; CDMASTERCADCELG: DR802R; PCODE: P01119035112; FNCLASSCODEG: P01-08
R325 R327 = R: ICX_PART_MODEL: RES_10K; FNPARTSNAMEG: CHIP RESISTOR (1608); OriginalSymbolOrigin: (5080,5080); FNCLASSCODEG: P01-08; PCODE: P01117053118; CDMASTERCADCELG: DR802R; USEWITHSCHEMA: YES; VAL2: 62.5mW; NUMBEROFELEMENT: 0; NOMINALRESISTAN: 10K; OUMEMAKERKATAMEI: RK73G1JTD103D; POWERRATING: 63m; MFMOUNTSYMBOLP: 80; RESISTANCETOLER: D; FUNCTION: G36010129493; OUMECLASSIFICATION: 表面実装用固定抵抗器; MOUNTINGFORMSMD: SMD; MFFORMINGDIVP: KC; MFPACKAGEMETHOP: S; OUMEMAKER: KOA ＫＯＡ; MFSOLDERINGPROP: .; MAXGCOUNT: 1
R328 R330 = R: SQ_PART_MODEL: RES_3.3K; FNPARTSNAMEG: CHIP RESISTOR (1608); USEINPARTSLIST: YES; OriginalSymbolOrigin: (5080,5080); TOLERANCE: F; ASIMVALUE: 3.3K; MAXGCOUNT: 1; COMPONENTNAME: G36010027027; MFSOLDERINGPROP: .; OUMEMAKER: ROH ロー・; MFPACKAGEMETHOP: S; MFFORMINGDIVP: KC; MOUNTINGFORMSMD: SMD; OUMECLASSIFICATION: 表面実装用固定抵抗器; MFMOUNTSYMBOLP: 80; POWERRATING: 63m; OUMEMAKERKATAMEI: MCR03EZPFX3301; NUMBEROFELEMENT: 0; VAL2: 62.5mW; VAL1: 3.3K(F); CDMASTERCADCELG: DR802R; PCODE: P01042250729; FNCLASSCODEG: P01-08
R329 = R: ICX_PART_MODEL: RES_3.3K; FNPARTSNAMEG: CHIP RESISTOR (1608); OriginalSymbolOrigin: (5080,5080); FNCLASSCODEG: P01-08; PCODE: P01042249822; CDMASTERCADCELG: DR802R; USEWITHSCHEMA: YES; VAL2: 62.5mW; NUMBEROFELEMENT: 0; NOMINALRESISTAN: 3.3K; OUMEMAKERKATAMEI: RR0816P-332-D; POWERRATING: 63m; MFMOUNTSYMBOLP: 80; RESISTANCETOLER: D; FUNCTION: G36010014485; OUMECLASSIFICATION: 表面実装用固定抵抗器; MOUNTINGFORMSMD: SMD; MFFORMINGDIVP: KC; MFPACKAGEMETHOP: S; OUMEMAKER: SSM 進工業; MFSOLDERINGPROP: .; MAXGCOUNT: 1
R331 = R: ICX_PART_MODEL: RES_3.3K; FNPARTSNAMEG: CHIP RESISTOR (1608); OriginalSymbolOrigin: (5080,5080); FNCLASSCODEG: P01-08; PCODE: P01117041115; CDMASTERCADCELG: DR802R; USEWITHSCHEMA: YES; VAL2: 62.5mW; NUMBEROFELEMENT: 0; NOMINALRESISTAN: 3.3K; OUMEMAKERKATAMEI: RK73G1JTD332D; POWERRATING: 63m; MFMOUNTSYMBOLP: 80; RESISTANCETOLER: D; FUNCTION: G36010129370; OUMECLASSIFICATION: 表面実装用固定抵抗器; MOUNTINGFORMSMD: SMD; MFFORMINGDIVP: KC; MFPACKAGEMETHOP: S; OUMEMAKER: KOA ＫＯＡ; MFSOLDERINGPROP: .; MAXGCOUNT: 1
U? = WAKU_DEF100: PLOTTIME: HH:MM; SAVEAREA0: 330961,54,387907,31546; TIME: 19:23:07; UPDATEUSER: t5459927; UPDATETIME: 15:33:42; SAVECOUNT: 6; OriginalSymbolOrigin: (10160,284480); DESIGNED: ***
